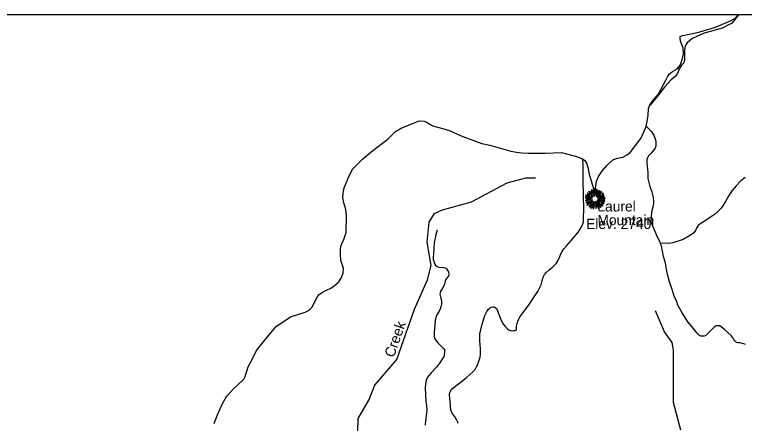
# Model space of a CAD drawing. Extents: x 990631 to 1056237, y 535999 to 585651.
# Drawn here: x 1001806 to 1012421, y 579700 to 585651 of the extents above; entities that cross this region are included whole.
import ezdxf

# ---------------------------------------------------------------- set-up
doc = ezdxf.new("R2010")
doc.units = 0
for name, color, linetype in [('Exist Boundary Political CountyLine', 7, 'Continuous'), ('Exist Geographical Mountain Summit CELL', 7, 'Continuous'), ('Exist Geographical Mountain Summit Elevation Number Label', 7, 'Continuous'), ('Exist Geographical Mountain Summit Label', 7, 'Continuous'), ('Exist Hydrographic Creek Single Shore', 7, 'Continuous'), ('Exist Hydrographic Creek Single Shore Label', 7, 'Continuous'), ('Exist Road Non-System Type 51', 7, 'Continuous'), ('Scratch_Level_3', 7, 'Continuous')]:
    doc.layers.add(name, color=color, linetype=linetype)

msp = doc.modelspace()

# ---------------------------------------------------------------- linework, layer by layer
at = {"layer": 'Exist Boundary Political CountyLine'}
for points in [[(1006556, 581816), (1006585, 581885), (1006589, 581953), (1006580, 581989), (1006551, 582074), (1006544, 582168), (1006544, 582232), (1006552, 582280), (1006600, 582393), (1006629, 582480), (1006633, 582728), (1006626, 582816), (1006595, 582909), (1006582, 582990), (1006584, 583054), (1006600, 583127), (1006659, 583271), (1006719, 583399), (1006868, 583546), (1007017, 583672), (1007234, 583838), (1007348, 583947), (1007428, 583996), (1007533, 584043), (1007641, 584087), (1007697, 584105), (1007761, 584101), (1007799, 584086), (1007889, 584031), (1008117, 583969), (1008324, 583878), (1008601, 583773), (1008718, 583751), (1008923, 583694), (1009024, 583665), (1009105, 583648), (1009185, 583641), (1009277, 583636), (1009521, 583634), (1009760, 583644), (1009978, 583585), (1010055, 583554), (1010094, 583531), (1010123, 583488), (1010143, 583431), (1010165, 583330), (1010221, 583132), (1010243, 583079), (1010256, 583123), (1010268, 583225), (1010298, 583294), (1010357, 583382), (1010418, 583456), (1010508, 583537), (1010577, 583563), (1010654, 583576), (1010717, 583608), (1010760, 583643), (1010915, 583848), (1010988, 584007), (1011007, 584097), (1011020, 584186), (1011028, 584280), (1011041, 584322), (1011079, 584384), (1011169, 584490), (1011280, 584698), (1011303, 584747), (1011329, 584783), (1011374, 584823), (1011445, 584861), (1011485, 584913), (1011516, 584994), (1011533, 585080), (1011531, 585162), (1011493, 585263), (1011486, 585306), (1011489, 585332), (1011519, 585345), (1011620, 585365), (1011771, 585402), (1012000, 585470), (1012227, 585563), (1012295, 585605), (1012336, 585651)], [(1004711, 579700), (1004757, 579824), (1004826, 579982), (1004869, 580059), (1004894, 580098), (1004988, 580205), (1005142, 580342), (1005162, 580381), (1005204, 580526), (1005269, 580650), (1005326, 580762), (1005462, 580931), (1005612, 581111), (1005672, 581153), (1005727, 581191), (1005821, 581250), (1006033, 581319), (1006089, 581349), (1006132, 581394), (1006175, 581474), (1006207, 581539), (1006234, 581578), (1006283, 581611), (1006334, 581635), (1006414, 581674), (1006455, 581705), (1006523, 581763), (1006556, 581816)]]:
    msp.add_lwpolyline(points, dxfattribs=at)
at = {"layer": 'Exist Geographical Mountain Summit CELL'}
for points in [[(1010158, 583077), (1010194, 583039), (1010197, 583042), (1010162, 583081)], [(1010186, 583078), (1010201, 583056), (1010203, 583058), (1010190, 583082)], [(1010197, 583100), (1010223, 583033), (1010226, 583034), (1010202, 583103)], [(1010230, 583048), (1010233, 583049), (1010224, 583097), (1010219, 583096)], [(1010235, 583109), (1010239, 583057), (1010242, 583058), (1010241, 583111)], [(1010251, 583055), (1010255, 583055), (1010259, 583103), (1010253, 583103)], [(1010263, 583027), (1010278, 583104), (1010272, 583106), (1010260, 583028)], [(1010266, 583005), (1010269, 583003), (1010318, 583088), (1010312, 583092)], [(1010281, 583062), (1010284, 583061), (1010294, 583088), (1010289, 583090)], [(1010287, 583007), (1010290, 583004), (1010345, 583069), (1010341, 583073)], [(1010325, 583078), (1010304, 583045), (1010307, 583044), (1010329, 583075)], [(1010109, 582982), (1010181, 582975), (1010182, 582978), (1010109, 582987)], [(1010112, 583003), (1010153, 582993), (1010154, 582997), (1010113, 583008)], [(1010115, 583022), (1010137, 583014), (1010138, 583016), (1010116, 583027)], [(1010121, 582964), (1010151, 582966), (1010151, 582970), (1010120, 582970)], [(1010137, 583033), (1010162, 583017), (1010165, 583019), (1010139, 583037)], [(1010138, 583052), (1010177, 583021), (1010179, 583024), (1010141, 583056)], [(1010153, 583005), (1010184, 582993), (1010185, 582995), (1010156, 583009)], [(1010154, 582955), (1010155, 582951), (1010188, 582959), (1010187, 582963)], [(1010166, 583049), (1010199, 583020), (1010201, 583022), (1010169, 583054)], [(1010190, 583011), (1010215, 582992), (1010217, 582995), (1010192, 583014)], [(1010190, 582981), (1010207, 582979), (1010207, 582981), (1010191, 582985)], [(1010209, 583024), (1010223, 583007), (1010225, 583009), (1010213, 583027)], [(1010241, 583036), (1010242, 583007), (1010245, 583007), (1010245, 583036)], [(1010284, 582987), (1010286, 582984), (1010335, 583020), (1010331, 583024)], [(1010300, 582971), (1010300, 582968), (1010330, 582968), (1010331, 582973)], [(1010301, 582984), (1010302, 582981), (1010380, 583010), (1010379, 583015)], [(1010343, 582970), (1010396, 582973), (1010396, 582978), (1010344, 582973)], [(1010345, 583012), (1010373, 583027), (1010370, 583032), (1010344, 583014)], [(1010345, 583035), (1010347, 583032), (1010370, 583048), (1010366, 583052)], [(1010347, 582984), (1010384, 582990), (1010382, 582996), (1010346, 582986)], [(1010358, 582958), (1010385, 582956), (1010385, 582960), (1010359, 582961)], [(1010108, 582944), (1010109, 582939), (1010145, 582950), (1010143, 582953)], [(1010118, 582916), (1010120, 582912), (1010166, 582932), (1010164, 582936)], [(1010129, 582880), (1010132, 582876), (1010160, 582897), (1010158, 582900)], [(1010135, 582901), (1010164, 582917), (1010162, 582921), (1010133, 582906)], [(1010160, 582860), (1010163, 582858), (1010203, 582905), (1010201, 582907)], [(1010171, 582910), (1010174, 582906), (1010209, 582935), (1010207, 582937)], [(1010175, 582891), (1010194, 582910), (1010191, 582912), (1010171, 582895)], [(1010200, 582891), (1010175, 582852), (1010178, 582850), (1010204, 582889)], [(1010181, 582941), (1010184, 582936), (1010212, 582952), (1010211, 582955)], [(1010185, 582833), (1010190, 582830), (1010201, 582855), (1010197, 582857)], [(1010203, 582870), (1010207, 582868), (1010234, 582927), (1010231, 582927)], [(1010210, 582919), (1010213, 582916), (1010223, 582933), (1010222, 582934)], [(1010215, 582835), (1010227, 582878), (1010223, 582878), (1010210, 582836)], [(1010225, 582825), (1010229, 582823), (1010242, 582913), (1010239, 582914)], [(1010250, 582928), (1010254, 582891), (1010258, 582892), (1010253, 582929)], [(1010256, 582870), (1010260, 582827), (1010264, 582828), (1010260, 582870)], [(1010266, 582920), (1010275, 582890), (1010279, 582892), (1010268, 582921)], [(1010276, 582853), (1010270, 582883), (1010267, 582883), (1010271, 582852)], [(1010274, 582940), (1010313, 582905), (1010315, 582909), (1010276, 582942)], [(1010281, 582918), (1010331, 582843), (1010335, 582846), (1010283, 582919)], [(1010281, 582875), (1010298, 582825), (1010302, 582827), (1010283, 582875)], [(1010286, 582957), (1010346, 582945), (1010347, 582950), (1010287, 582961)], [(1010291, 582880), (1010307, 582851), (1010311, 582853), (1010295, 582882)], [(1010299, 582938), (1010378, 582899), (1010379, 582905), (1010301, 582940)], [(1010313, 582892), (1010343, 582863), (1010346, 582865), (1010315, 582894)], [(1010330, 582892), (1010360, 582867), (1010363, 582870), (1010331, 582895)], [(1010339, 582903), (1010364, 582890), (1010366, 582894), (1010341, 582907)], [(1010353, 582927), (1010374, 582919), (1010376, 582924), (1010354, 582931)], [(1010362, 582941), (1010391, 582934), (1010391, 582939), (1010363, 582945)]]:
    msp.add_lwpolyline(points, close=True, dxfattribs=at)
at = {"layer": 'Exist Hydrographic Creek Single Shore'}
for points in [[(1006792, 579393), (1006804, 579770), (1006956, 580040), (1007046, 580258), (1007367, 580629), (1007625, 581362), (1007814, 581791), (1007863, 581997), (1007808, 582340), (1007834, 582631), (1007913, 582754), (1008032, 582808), (1008453, 582927), (1008970, 583202), (1009240, 583276), (1009381, 583273)], [(1011494, 579600), (1011390, 580003), (1011391, 580771), (1011369, 580880), (1011258, 581033), (1011126, 581337)]]:
    msp.add_lwpolyline(points, dxfattribs=at)
at = {"layer": 'Exist Road Non-System Type 51'}
msp.add_line((1011457, 584876), (1011473, 584862), dxfattribs=at)
for points in [[(1012338, 585651), (1012296, 585599), (1012263, 585554), (1012232, 585523), (1012181, 585497), (1012112, 585459), (1011998, 585423), (1011908, 585402), (1011837, 585380), (1011727, 585332), (1011666, 585304), (1011625, 585275), (1011588, 585238), (1011567, 585213), (1011558, 585191), (1011550, 585135), (1011551, 585033), (1011548, 584991), (1011538, 584950), (1011509, 584921), (1011473, 584862)], [(1011473, 584862), (1011471, 584858), (1011447, 584795), (1011414, 584752), (1011358, 584700), (1011258, 584597), (1011189, 584509), (1011049, 584334)], [(1010992, 584026), (1011018, 584002), (1011069, 583951), (1011103, 583893), (1011120, 583859), (1011132, 583810), (1011134, 583762), (1011133, 583734), (1011116, 583699), (1011062, 583629), (1011027, 583594), (1011012, 583568), (1011003, 583537), (1011001, 583489), (1011010, 583402), (1011017, 583354), (1011018, 583264), (1011046, 583147), (1011075, 583070), (1011091, 583015), (1011096, 582979), (1011097, 582941), (1011098, 582899), (1011083, 582829), (1011069, 582776), (1011063, 582700), (1011061, 582638), (1011070, 582608), (1011157, 582407), (1011191, 582345), (1011198, 582323)], [(1009938, 582405), (1010001, 582485), (1010024, 582514), (1010043, 582546), (1010058, 582573), (1010073, 582603), (1010080, 582635), (1010080, 582691), (1010084, 582813), (1010078, 583235), (1010076, 583459), (1010070, 583545)], [(1012431, 583281), (1012371, 583229)], [(1012371, 583229), (1012301, 583159), (1012245, 583089), (1012194, 583016), (1012124, 582889), (1012076, 582830), (1011999, 582753), (1011928, 582703), (1011850, 582648), (1011801, 582619), (1011772, 582600), (1011749, 582579), (1011730, 582550), (1011709, 582508), (1011686, 582473), (1011622, 582431), (1011530, 582378), (1011379, 582327), (1011324, 582319), (1011198, 582323)], [(1007951, 582514), (1007932, 582444), (1007918, 582377), (1007909, 582333), (1007904, 582245), (1007897, 582175), (1007895, 582113), (1007896, 582085), (1007902, 582061), (1007913, 582030), (1007928, 582004), (1007953, 581985), (1007975, 581976), (1008053, 581968), (1008072, 581963), (1008088, 581949), (1008109, 581928), (1008118, 581900), (1008123, 581873), (1008116, 581844), (1008083, 581803), (1008068, 581771), (1008054, 581714), (1008024, 581660), (1008003, 581627), (1007994, 581603), (1007992, 581582), (1008004, 581525), (1008016, 581487), (1008015, 581441), (1008003, 581379), (1007981, 581336), (1007952, 581289), (1007934, 581243), (1007921, 581200), (1007917, 581136), (1007909, 581026), (1007911, 580966), (1007920, 580930), (1007956, 580880), (1008024, 580812), (1008043, 580789), (1008057, 580769), (1008060, 580747), (1008059, 580727), (1008047, 580675), (1007988, 580577), (1007944, 580519), (1007867, 580437), (1007830, 580400), (1007807, 580365), (1007794, 580329), (1007784, 580276), (1007780, 580212), (1007788, 580025), (1007795, 579961), (1007803, 579891), (1007793, 579817), (1007782, 579741), (1007778, 579673)], [(1008259, 579699), (1008250, 579726), (1008239, 579748), (1008214, 579793), (1008181, 579834), (1008161, 579869), (1008152, 579901), (1008144, 579925), (1008144, 579967), (1008137, 580068), (1008131, 580108), (1008134, 580138), (1008144, 580164), (1008162, 580199), (1008283, 580291), (1008373, 580362), (1008429, 580410), (1008470, 580449), (1008510, 580497), (1008525, 580525), (1008538, 580547), (1008553, 580590), (1008567, 580636), (1008576, 580665), (1008581, 580701), (1008582, 580787), (1008575, 580902), (1008575, 581008), (1008585, 581063), (1008605, 581145), (1008646, 581270), (1008674, 581329), (1008699, 581362), (1008719, 581379), (1008734, 581391), (1008762, 581398), (1008778, 581397), (1008796, 581389), (1008815, 581372), (1008832, 581341), (1008859, 581261), (1008876, 581212), (1008904, 581161), (1008943, 581112), (1008973, 581077), (1008995, 581064), (1009013, 581055), (1009029, 581055), (1009057, 581050), (1009073, 581051), (1009089, 581055), (1009101, 581058), (1009105, 581070), (1009105, 581114), (1009116, 581156), (1009128, 581205), (1009158, 581255), (1009233, 581352), (1009279, 581415), (1009365, 581542), (1009418, 581620), (1009439, 581667), (1009465, 581718), (1009479, 581776), (1009495, 581828), (1009512, 581867), (1009537, 581896), (1009582, 581935), (1009626, 581971), (1009669, 582012), (1009686, 582031), (1009702, 582055), (1009713, 582083), (1009733, 582114), (1009752, 582171), (1009768, 582205), (1009795, 582240), (1009840, 582288), (1009938, 582405)], [(1012438, 580851), (1012412, 580860), (1012393, 580864), (1012357, 580872), (1012323, 580873), (1012305, 580879), (1012291, 580892), (1012280, 580904), (1012268, 580920), (1012259, 580939), (1012228, 580978), (1012129, 581067), (1012063, 581120), (1012037, 581122), (1012017, 581121), (1012001, 581118), (1011988, 581104), (1011939, 581058), (1011904, 581025), (1011858, 580978), (1011836, 580971), (1011810, 580970), (1011784, 580971), (1011766, 580981), (1011735, 581012), (1011654, 581111), (1011599, 581181), (1011515, 581308), (1011451, 581420), (1011436, 581469), (1011397, 581554), (1011370, 581649), (1011330, 581762), (1011296, 581886), (1011271, 582033), (1011246, 582131), (1011213, 582283), (1011198, 582323)]]:
    msp.add_lwpolyline(points, dxfattribs=at)
at = {"layer": 'Scratch_Level_3'}
msp.add_lwpolyline([(1056237, 535999), (990631, 535999), (990631, 585651), (1056237, 585651)], close=True, dxfattribs=at)

# ---------------------------------------------------------------- texts
at = {"layer": 'Exist Geographical Mountain Summit Elevation Number Label'}
msp.add_text('Elev. 2740', height=150, dxfattribs=at).set_placement((1010119, 582530))
at = {"layer": 'Exist Geographical Mountain Summit Label'}
for s, p in [('Laurel', (1010283, 582785)), ('Mountain', (1010283, 582586))]:
    msp.add_text(s, height=150, dxfattribs=at).set_placement(p)
at = {"layer": 'Exist Hydrographic Creek Single Shore Label'}
msp.add_text('Creek', height=150, rotation=70.627, dxfattribs=at).set_placement((1007322, 580650))

doc.saveas('drawing.dxf')
